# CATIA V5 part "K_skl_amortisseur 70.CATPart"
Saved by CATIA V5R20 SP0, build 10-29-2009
Part number: skl_amortisseur 70
Publications: "longueur verin commande", "longueur axe pivot", "liaison 51/70 sur 70", "droite appui verin commande", "Plan.-55", "Droite.1", "Droite.3"
Bounding box of the stored display mesh (mm): x -55 to 95, y -495 to 93.839, z 505.724 to 665
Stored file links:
  G:\Khaled_CFAO_2011\SIL\SIL_GR2\mdardier\Khaled\CAD_ThinkMOTION\K_skl_amortisseur 70.CATPart
  G:\Khaled_CFAO_2011\SIL\SIL_GR2\mdardier\Khaled\CAD_ThinkMOTION\K_skl_ass_tandem.CATProduct
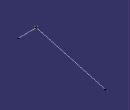
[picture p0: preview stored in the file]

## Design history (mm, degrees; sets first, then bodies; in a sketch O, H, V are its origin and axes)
External parameters (linked from other documents)
  `External.longueur verin commande` = 620 mm
  `External.longueur axe pivot` = 150 mm
Set1
  Point1 "liaison 51/70 sur 70": linked copy from another document
  Line1 "droite appui verin commande": linked copy from another document
  Plane1 "Plan.-55": linked copy from another document
Set2
  Line2: type PtDir, RefPoint Point1, Direction Line1, Start 0, End 610 {= `External.longueur verin commande` -0.01}
  Line3: type Normal, RefPoint Point1, RefSkin Plane1, Start 0, End 150 {= `External.longueur axe pivot`}
Body1 (main body)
